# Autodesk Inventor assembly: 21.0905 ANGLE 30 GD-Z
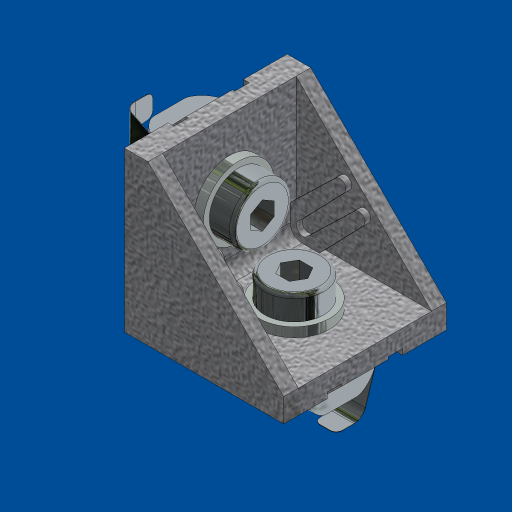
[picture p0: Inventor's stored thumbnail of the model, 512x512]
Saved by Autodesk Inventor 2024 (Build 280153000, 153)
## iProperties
Created: 2017-01
Part Number: 21.0905 ANGLE 30 GD-Z
Document SubType Name: Assembly
Designer: Admin
Mass: 36.9261 g
Surface Area: 75.3476 cm^2
Volume: 9.00016 cm^3
Density: 4.10283 g/cm^3
Author: Admin
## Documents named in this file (5)
- L:\INVENTOR LIBRARIES\PARTS LIBRARY\30 SERIES\21.0905 ANGLE 30 GD-Z.iam
- L:\INVENTOR LIBRARIES\PARTS LIBRARY\30 SERIES\SUBCOMPONENTS\21.0905_2 ANGLE 30 AL GD-Z GUSSET.ipt
- L:\INVENTOR LIBRARIES\PARTS LIBRARY\30 SERIES\21.2342_2 M6 SQUARE NUT 30 POS FXG.ipt
- L:\INVENTOR LIBRARIES\PARTS LIBRARY\FASTENING ELEMENTS\SCREWS CAP\21.1367 M6X14.ipt
- L:\INVENTOR LIBRARIES\PARTS LIBRARY\FASTENING ELEMENTS\WASHERS\21.1126 M6 ROUND WASHER.ipt
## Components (7 placed, 4 different names)
1. 21.0905_2 ANGLE 30 AL GD-Z GUSSET:1 — Insert:1, Insert:2, Mate:2, Angle:1, Mate:4, Angle:2, Insert:3, Insert:4
2. 21.1367 M6X14 SHCS:1 — Insert:1, Mate:1
3. 21.1367 M6X14 SHCS:2 — Insert:2, Mate:3
4. 21.2342_2 M6 SQUARE NUT 30 POS FXG:1 — Mate:1, Mate:2, Angle:1
5. 21.2342_2 M6 SQUARE NUT 30 POS FXG:2 — Mate:3, Mate:4, Angle:2
6. 21.1126 M6 ROUND WASHER:1 — Insert:3
7. 21.1126 M6 ROUND WASHER:2 — Insert:4
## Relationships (10: Insert 4, Mate 4, Angle 2)
- Insert:1: 21.0905_2 ANGLE 30 AL GD-Z GUSSET:1 ↔ 21.1367 M6X14 SHCS:1
- Insert:2: 21.0905_2 ANGLE 30 AL GD-Z GUSSET:1 ↔ 21.1367 M6X14 SHCS:2
- Mate:1: 21.1367 M6X14 SHCS:1 ↔ 21.2342_2 M6 SQUARE NUT 30 POS FXG:1
- Mate:2: 21.0905_2 ANGLE 30 AL GD-Z GUSSET:1 ↔ 21.2342_2 M6 SQUARE NUT 30 POS FXG:1
- Angle:1: 21.0905_2 ANGLE 30 AL GD-Z GUSSET:1 ↔ 21.2342_2 M6 SQUARE NUT 30 POS FXG:1
- Mate:3: 21.1367 M6X14 SHCS:2 ↔ 21.2342_2 M6 SQUARE NUT 30 POS FXG:2
- Mate:4: 21.0905_2 ANGLE 30 AL GD-Z GUSSET:1 ↔ 21.2342_2 M6 SQUARE NUT 30 POS FXG:2
- Angle:2: 21.0905_2 ANGLE 30 AL GD-Z GUSSET:1 ↔ 21.2342_2 M6 SQUARE NUT 30 POS FXG:2
- Insert:3: 21.0905_2 ANGLE 30 AL GD-Z GUSSET:1 ↔ 21.1126 M6 ROUND WASHER:1
- Insert:4: 21.0905_2 ANGLE 30 AL GD-Z GUSSET:1 ↔ 21.1126 M6 ROUND WASHER:2
